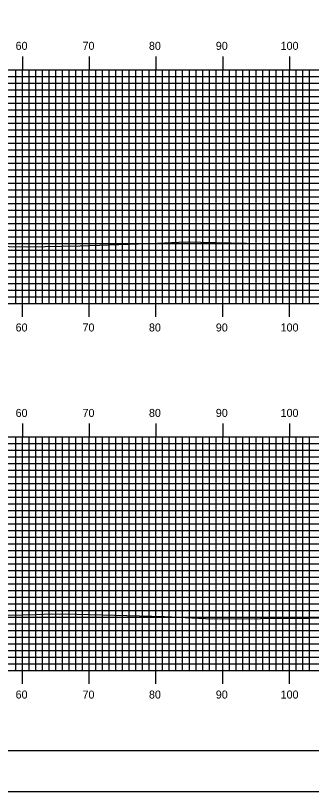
# Model space of a CAD drawing. Extents: x 1811767 to 1812110, y 442591 to 442811.
# Drawn here: x 1811991.9 to 1812036.2, y 442590.5 to 442706.8 of the extents above; entities that cross this region are included whole.
import ezdxf

# ---------------------------------------------------------------- set-up
doc = ezdxf.new("R2010")
doc.units = 0
for name, color, linetype in [('BORDER', 7, 'Continuous'), ('H_V ANNOTATION', 7, 'Continuous'), ('MAJOR', 7, 'Continuous'), ('MINOR', 7, 'Continuous'), ('PLOT BOUNDARY', 7, 'Continuous'), ('S_Roadway_Centerline', 7, 'Continuous')]:
    doc.layers.add(name, color=color, linetype=linetype)

msp = doc.modelspace()

# ---------------------------------------------------------------- linework, layer by layer
at = {"layer": 'BORDER'}
msp.add_lwpolyline([(1811783.32, 442596.67), (1812103.32, 442596.67), (1812103.32, 442806.67), (1811783.32, 442806.67)], close=True, dxfattribs=at)
at = {"layer": 'MAJOR'}
for p, q in [((1811992.92, 442700.67), (1811992.92, 442698.67)), ((1812002.92, 442700.67), (1812002.92, 442698.67)), ((1812012.92, 442700.67), (1812012.92, 442698.67)), ((1812022.92, 442700.67), (1812022.92, 442698.67)), ((1812032.92, 442700.67), (1812032.92, 442698.67)), ((1811792.92, 442698.67), (1812072.92, 442698.67)), ((1811792.92, 442698.67), (1812072.92, 442698.67)), ((1811992.92, 442663.67), (1811992.92, 442698.67)), ((1812002.92, 442663.67), (1812002.92, 442698.67)), ((1812012.92, 442663.67), (1812012.92, 442698.67)), ((1812022.92, 442663.67), (1812022.92, 442698.67)), ((1812032.92, 442663.67), (1812032.92, 442698.67)), ((1811792.92, 442693.67), (1812072.92, 442693.67)), ((1811792.92, 442688.67), (1812072.92, 442688.67)), ((1811792.92, 442683.67), (1812072.92, 442683.67)), ((1811792.92, 442678.67), (1812072.92, 442678.67)), ((1811792.92, 442673.67), (1812072.92, 442673.67)), ((1811792.92, 442668.67), (1812072.92, 442668.67)), ((1811792.92, 442663.67), (1812072.92, 442663.67)), ((1811792.92, 442663.67), (1812072.92, 442663.67)), ((1811992.92, 442661.66), (1811992.92, 442663.67)), ((1812002.92, 442661.66), (1812002.92, 442663.67)), ((1812012.92, 442661.66), (1812012.92, 442663.67)), ((1812022.92, 442661.66), (1812022.92, 442663.67)), ((1812032.92, 442661.66), (1812032.92, 442663.67)), ((1811992.92, 442645.67), (1811992.92, 442643.67)), ((1812002.92, 442645.67), (1812002.92, 442643.67)), ((1812012.92, 442645.67), (1812012.92, 442643.67)), ((1812022.92, 442645.67), (1812022.92, 442643.67)), ((1812032.92, 442645.67), (1812032.92, 442643.67)), ((1811792.92, 442643.67), (1812072.92, 442643.67)), ((1811792.92, 442643.67), (1812072.92, 442643.67)), ((1811992.92, 442608.67), (1811992.92, 442643.67)), ((1812002.92, 442608.67), (1812002.92, 442643.67)), ((1812012.92, 442608.67), (1812012.92, 442643.67)), ((1812022.92, 442608.67), (1812022.92, 442643.67)), ((1812032.92, 442608.67), (1812032.92, 442643.67)), ((1811792.92, 442638.67), (1812072.92, 442638.67)), ((1811792.92, 442633.67), (1812072.92, 442633.67)), ((1811792.92, 442628.67), (1812072.92, 442628.67)), ((1811792.92, 442623.67), (1812072.92, 442623.67)), ((1811792.92, 442618.67), (1812072.92, 442618.67)), ((1811792.92, 442613.67), (1812072.92, 442613.67)), ((1811792.92, 442608.67), (1812072.92, 442608.67)), ((1811792.92, 442608.67), (1812072.92, 442608.67)), ((1811992.92, 442606.66), (1811992.92, 442608.67)), ((1812002.92, 442606.66), (1812002.92, 442608.67)), ((1812012.92, 442606.66), (1812012.92, 442608.67)), ((1812022.92, 442606.66), (1812022.92, 442608.67)), ((1812032.92, 442606.66), (1812032.92, 442608.67))]:
    msp.add_line(p, q, dxfattribs=at)
at = {"layer": 'MINOR'}
for p, q in [((1811991.92, 442663.67), (1811991.92, 442698.67)), ((1811993.92, 442663.67), (1811993.92, 442698.67)), ((1811994.92, 442663.67), (1811994.92, 442698.67)), ((1811995.92, 442663.67), (1811995.92, 442698.67)), ((1811996.92, 442663.67), (1811996.92, 442698.67)), ((1811997.92, 442663.67), (1811997.92, 442698.67)), ((1811998.92, 442663.67), (1811998.92, 442698.67)), ((1811999.92, 442663.67), (1811999.92, 442698.67)), ((1812000.92, 442663.67), (1812000.92, 442698.67)), ((1812001.92, 442663.67), (1812001.92, 442698.67)), ((1812003.92, 442663.67), (1812003.92, 442698.67)), ((1812004.92, 442663.67), (1812004.92, 442698.67)), ((1812005.92, 442663.67), (1812005.92, 442698.67)), ((1812006.92, 442663.67), (1812006.92, 442698.67)), ((1812007.92, 442663.67), (1812007.92, 442698.67)), ((1812008.92, 442663.67), (1812008.92, 442698.67)), ((1812009.92, 442663.67), (1812009.92, 442698.67)), ((1812010.92, 442663.67), (1812010.92, 442698.67)), ((1812011.92, 442663.67), (1812011.92, 442698.67)), ((1812013.92, 442663.67), (1812013.92, 442698.67)), ((1812014.92, 442663.67), (1812014.92, 442698.67)), ((1812015.92, 442663.67), (1812015.92, 442698.67)), ((1812016.92, 442663.67), (1812016.92, 442698.67)), ((1812017.92, 442663.67), (1812017.92, 442698.67)), ((1812018.92, 442663.67), (1812018.92, 442698.67)), ((1812019.92, 442663.67), (1812019.92, 442698.67)), ((1812020.92, 442663.67), (1812020.92, 442698.67)), ((1812021.92, 442663.67), (1812021.92, 442698.67)), ((1812023.92, 442663.67), (1812023.92, 442698.67)), ((1812024.92, 442663.67), (1812024.92, 442698.67)), ((1812025.92, 442663.67), (1812025.92, 442698.67)), ((1812026.92, 442663.67), (1812026.92, 442698.67)), ((1812027.92, 442663.67), (1812027.92, 442698.67)), ((1812028.92, 442663.67), (1812028.92, 442698.67)), ((1812029.92, 442663.67), (1812029.92, 442698.67)), ((1812030.92, 442663.67), (1812030.92, 442698.67)), ((1812031.92, 442663.67), (1812031.92, 442698.67)), ((1812033.92, 442663.67), (1812033.92, 442698.67)), ((1812034.92, 442663.67), (1812034.92, 442698.67)), ((1812035.92, 442663.67), (1812035.92, 442698.67)), ((1811792.92, 442697.67), (1812072.92, 442697.67)), ((1811792.92, 442696.67), (1812072.92, 442696.67)), ((1811792.92, 442695.67), (1812072.92, 442695.67)), ((1811792.92, 442694.67), (1812072.92, 442694.67)), ((1811792.92, 442692.67), (1812072.92, 442692.67)), ((1811792.92, 442691.67), (1812072.92, 442691.67)), ((1811792.92, 442690.67), (1812072.92, 442690.67)), ((1811792.92, 442689.67), (1812072.92, 442689.67)), ((1811792.92, 442687.67), (1812072.92, 442687.67)), ((1811792.92, 442686.67), (1812072.92, 442686.67)), ((1811792.92, 442685.67), (1812072.92, 442685.67)), ((1811792.92, 442684.67), (1812072.92, 442684.67)), ((1811792.92, 442682.67), (1812072.92, 442682.67)), ((1811792.92, 442681.67), (1812072.92, 442681.67)), ((1811792.92, 442680.67), (1812072.92, 442680.67)), ((1811792.92, 442679.67), (1812072.92, 442679.67)), ((1811792.92, 442677.67), (1812072.92, 442677.67)), ((1811792.92, 442676.67), (1812072.92, 442676.67)), ((1811792.92, 442675.67), (1812072.92, 442675.67)), ((1811792.92, 442674.67), (1812072.92, 442674.67)), ((1811792.92, 442672.67), (1812072.92, 442672.67)), ((1811792.92, 442671.67), (1812072.92, 442671.67)), ((1811792.92, 442670.67), (1812072.92, 442670.67)), ((1811792.92, 442669.67), (1812072.92, 442669.67)), ((1811792.92, 442667.67), (1812072.92, 442667.67)), ((1811792.92, 442666.67), (1812072.92, 442666.67)), ((1811792.92, 442665.67), (1812072.92, 442665.67)), ((1811792.92, 442664.67), (1812072.92, 442664.67)), ((1811991.92, 442608.67), (1811991.92, 442643.67)), ((1811993.92, 442608.67), (1811993.92, 442643.67)), ((1811994.92, 442608.67), (1811994.92, 442643.67)), ((1811995.92, 442608.67), (1811995.92, 442643.67)), ((1811996.92, 442608.67), (1811996.92, 442643.67)), ((1811997.92, 442608.67), (1811997.92, 442643.67)), ((1811998.92, 442608.67), (1811998.92, 442643.67)), ((1811999.92, 442608.67), (1811999.92, 442643.67)), ((1812000.92, 442608.67), (1812000.92, 442643.67)), ((1812001.92, 442608.67), (1812001.92, 442643.67)), ((1812003.92, 442608.67), (1812003.92, 442643.67)), ((1812004.92, 442608.67), (1812004.92, 442643.67)), ((1812005.92, 442608.67), (1812005.92, 442643.67)), ((1812006.92, 442608.67), (1812006.92, 442643.67)), ((1812007.92, 442608.67), (1812007.92, 442643.67)), ((1812008.92, 442608.67), (1812008.92, 442643.67)), ((1812009.92, 442608.67), (1812009.92, 442643.67)), ((1812010.92, 442608.67), (1812010.92, 442643.67)), ((1812011.92, 442608.67), (1812011.92, 442643.67)), ((1812013.92, 442608.67), (1812013.92, 442643.67)), ((1812014.92, 442608.67), (1812014.92, 442643.67)), ((1812015.92, 442608.67), (1812015.92, 442643.67)), ((1812016.92, 442608.67), (1812016.92, 442643.67)), ((1812017.92, 442608.67), (1812017.92, 442643.67)), ((1812018.92, 442608.67), (1812018.92, 442643.67)), ((1812019.92, 442608.67), (1812019.92, 442643.67)), ((1812020.92, 442608.67), (1812020.92, 442643.67)), ((1812021.92, 442608.67), (1812021.92, 442643.67)), ((1812023.92, 442608.67), (1812023.92, 442643.67)), ((1812024.92, 442608.67), (1812024.92, 442643.67)), ((1812025.92, 442608.67), (1812025.92, 442643.67)), ((1812026.92, 442608.67), (1812026.92, 442643.67)), ((1812027.92, 442608.67), (1812027.92, 442643.67)), ((1812028.92, 442608.67), (1812028.92, 442643.67)), ((1812029.92, 442608.67), (1812029.92, 442643.67)), ((1812030.92, 442608.67), (1812030.92, 442643.67)), ((1812031.92, 442608.67), (1812031.92, 442643.67)), ((1812033.92, 442608.67), (1812033.92, 442643.67)), ((1812034.92, 442608.67), (1812034.92, 442643.67)), ((1812035.92, 442608.67), (1812035.92, 442643.67)), ((1811792.92, 442642.67), (1812072.92, 442642.67)), ((1811792.92, 442641.67), (1812072.92, 442641.67)), ((1811792.92, 442640.67), (1812072.92, 442640.67)), ((1811792.92, 442639.67), (1812072.92, 442639.67)), ((1811792.92, 442637.67), (1812072.92, 442637.67)), ((1811792.92, 442636.67), (1812072.92, 442636.67)), ((1811792.92, 442635.67), (1812072.92, 442635.67)), ((1811792.92, 442634.67), (1812072.92, 442634.67)), ((1811792.92, 442632.67), (1812072.92, 442632.67)), ((1811792.92, 442631.67), (1812072.92, 442631.67)), ((1811792.92, 442630.67), (1812072.92, 442630.67)), ((1811792.92, 442629.67), (1812072.92, 442629.67)), ((1811792.92, 442627.67), (1812072.92, 442627.67)), ((1811792.92, 442626.67), (1812072.92, 442626.67)), ((1811792.92, 442625.67), (1812072.92, 442625.67)), ((1811792.92, 442624.67), (1812072.92, 442624.67)), ((1811792.92, 442622.67), (1812072.92, 442622.67)), ((1811792.92, 442621.67), (1812072.92, 442621.67)), ((1811792.92, 442620.67), (1812072.92, 442620.67)), ((1811792.92, 442619.67), (1812072.92, 442619.67)), ((1811792.92, 442617.67), (1812072.92, 442617.67)), ((1811792.92, 442616.67), (1812072.92, 442616.67)), ((1811792.92, 442615.67), (1812072.92, 442615.67)), ((1811792.92, 442614.67), (1812072.92, 442614.67)), ((1811792.92, 442612.67), (1812072.92, 442612.67)), ((1811792.92, 442611.67), (1812072.92, 442611.67)), ((1811792.92, 442610.67), (1812072.92, 442610.67)), ((1811792.92, 442609.67), (1812072.92, 442609.67))]:
    msp.add_line(p, q, dxfattribs=at)
at = {"layer": 'PLOT BOUNDARY'}
msp.add_lwpolyline([(1811767.13, 442590.55), (1812107.13, 442590.55), (1812107.13, 442810.55), (1811767.13, 442810.55)], close=True, dxfattribs=at)
at = {"layer": 'S_Roadway_Centerline'}
for points in [[(1811979.59, 442672.39), (1811993.71, 442672.13), (1812001.57, 442672.31), (1812013.17, 442672.71), (1812017.34, 442672.89), (1812019.62, 442672.87), (1812031.04, 442672.58), (1812038.76, 442672.72), (1812053.11, 442671.61), (1812055.91, 442671.31), (1812057.19, 442671.32), (1812061.48, 442671.27), (1812072.92, 442671.09)], [(1811984.1, 442616.8), (1811994.98, 442617.07), (1811997.24, 442617.18), (1812001.07, 442617.12), (1812014.22, 442616.75), (1812021.38, 442616.44), (1812035.8, 442616.52), (1812044.42, 442616.73), (1812049.88, 442616.05), (1812066.64, 442616.35), (1812068.4, 442616.3), (1812068.88, 442616.31), (1812072.92, 442616.12)]]:
    msp.add_lwpolyline(points, dxfattribs=at)

# ---------------------------------------------------------------- texts
at = {"layer": 'H_V ANNOTATION'}
for s, p in [('60', (1811991.89, 442701.67)), ('70', (1812001.92, 442701.67)), ('80', (1812011.87, 442701.67)), ('90', (1812021.89, 442701.67)), ('100', (1812031.6, 442701.67)), ('60', (1811991.89, 442659.47)), ('70', (1812001.92, 442659.47)), ('80', (1812011.87, 442659.47)), ('90', (1812021.89, 442659.47)), ('100', (1812031.6, 442659.47)), ('60', (1811991.89, 442646.67)), ('70', (1812001.92, 442646.67)), ('80', (1812011.87, 442646.67)), ('90', (1812021.89, 442646.67)), ('100', (1812031.6, 442646.67)), ('60', (1811991.89, 442604.47)), ('70', (1812001.92, 442604.47)), ('80', (1812011.87, 442604.47)), ('90', (1812021.89, 442604.47)), ('100', (1812031.6, 442604.47))]:
    msp.add_text(s, height=1.2, dxfattribs=at).set_placement(p)

doc.saveas('drawing.dxf')
